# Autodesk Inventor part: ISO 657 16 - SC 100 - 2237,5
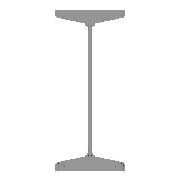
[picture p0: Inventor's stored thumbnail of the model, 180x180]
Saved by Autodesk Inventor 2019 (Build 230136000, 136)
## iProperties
_CCFamilyMember: 1
_CCFamilyDisplayName: ISO 657/16 - 1980 - Poutres en acier laminées à chaud - Partie 16: profilés en H (série métrique) - Cotes et propriétés de section
_FrameMemberDoc: Frame Member File
_Version: 15.0.0
_GetPNFromCC: 1
Created: 2018-07
Part Number: ISO 657 16 - SC 100 - 2237,5
Material: Acier, doux
Description: Poutres en acier laminées à chaud - Partie 16: profilés en H (série métrique) - Cotes et propriétés de section
Document SubType Name: Modeling
Standard: ISO
Designer: Fabian Perrée
Standard Revision: First edition 1980-02-15
Standards Organization: ISO
Language: fr-FR
Size Designation: SC 100
Categories: <MemberInstance><Categories><Category DisplayName="Profilés" InternalName="089c4875-fa83-4c05-b084-43b9cc11f5ed" Mnemonic="GRDR"><CategoryParameter DisplayName=
Stock Number: SC 100
Density: 7.85 g/cm^3
Appearance: Semi-poli
Mass: 44309.5 g
Surface Area: 12051.7 cm^2
Volume: 5644.52 cm^3
IsCustomPart: 1
G_W: 100,000 mm
G_H: 100,000 mm
+00612AE5-4A21-40A4-B490-CD8F624E81A5+DETAILDECOUPE1: Angle de coupe 90,00 deg
+1A323659-953F-4F35-8181-0827E3868009+DETAILDECOUPE2: Angle de coupe 67,38 deg
G_L: 2237,500 mm
Author: Fabian Perrée
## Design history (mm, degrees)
node "Plan de départ"
node "Plan de fin"
sketch "Esquisse"
  geometry: L1 (-3, 0)-(-3, -26.266); L2 (-13.33, -38.149)-(-44.835, -42.577); L3 (-50, -48.518)-(-50, -50); L4 (-50, -50)-(0, -50); L5 (-26.5, -50)-(-26.5, -40); L6 (-61.333, 0)-(81.777, 0); L7 (0, 0)-(0, -50); L8 (0, -60)-(0, 80); L9 (3, 0)-(3, -26.266); L10 (13.33, -38.149)-(44.835, -42.577); L11 (50, -48.518)-(50, -50); L12 (50, -50)-(0, -50); L13 (-3, 0)-(0, 0); L14 (-3, 0)-(-3, 26.266); L15 (-13.33, 38.149)-(-44.835, 42.577); L16 (-50, 48.518)-(-50, 50); L17 (-50, 50)-(0, 50); L18 (50, 48.518)-(50, 50); L19 (13.33, 38.149)-(44.835, 42.577); L20 (3, 0)-(3, 26.266); L21 (50, 50)-(0, 50); L22 (0, 108)-(0, -88) reference; L23 (-89.955, 0)-(110.399, 0) reference; A1 r 6 centre (-44, 48.518) between (-50, 48.518) and (-44.835, 42.577); A2 r 6 centre (44, 48.518) between (44.835, 42.577) and (50, 48.518); A3 r 6 centre (44, -48.518) between (50, -48.518) and (44.835, -42.577); A4 r 6 centre (-44, -48.518) between (-44.835, -42.577) and (-50, -48.518); A5 r 12 centre (-15, 26.266) between (-3, 26.266) and (-13.33, 38.149); A6 r 12 centre (15, 26.266) between (13.33, 38.149) and (3, 26.266); A7 r 12 centre (15, -26.266) between (3, -26.266) and (13.33, -38.149); A8 r 12 centre (-15, -26.266) between (-13.33, -38.149) and (-3, -26.266); 14 further points
  constraints: 42 end point, 24 point on line, 17 symmetric about line, 16 point on circle, 16 tangent, 8 centre point, 6 equal radius, 4 collinear, 2 perpendicular, 12 other
  dimensions: "d1" = 10 vertical distance of L3.end L5.end (= G_T1); "d2" = 23.5 distance between parallel lines of L5 L3 (= -0.25 x G_T + 0.25 x G_W); "d3" = 3 distance between parallel lines of L1 L7 (= 0.5 x G_T); "d4" = 50 distance between parallel lines of L7 L3 (= 0.5 x G_W); "d9" = 50 distance from line of L1.start L4 (= 0.5 x G_H); "d14" = 98 deg angle of L2 L1 (= G_NG); "d15" = 6 radius of A1 (= G_ER); "d16" = 12 radius of A5 (= G_IR)
extrude "Corps" new body sketch "Esquisse" stored distance "d5" = 2237.5 (= G_L); taper "d6" = 0 deg
node "Driven Length"
  sketch "Sketch3"
    geometry: L1 (0, 0)-(10, 0) reference
    constraints: 2 end point, 1 horizontal
  workplane "Work Plane3"
  sketch "Sketch4"
    geometry: L1 (-2, 87.5)-(12, 87.5) reference; L2 (-2, 2325)-(12, 2325) reference
    dimensions: "d20" = 2237.5 distance between parallel lines of L1 L2 (derived)
node "Plan de construction4"
feature "Scission1"
node "Plan de construction5"
feature "Scission2"
body "Solid1"
other parameters: "G_W" = 100 (= G_H) [user parameter; used in 2 equation terms], "G_H" = 100 [user parameter; used in 2 equation terms], "G_T" = 6 [user parameter; used in 2 equation terms], "G_T1" = 10 [user parameter; used in 1 equation term], "G_L" = 2237.5 (= d20) [user parameter; used in 1 equation term], "G_ER" = 6 [user parameter; used in 1 equation term], "G_IR" = 12 [user parameter; used in 1 equation term], "G_NG" = 98 deg [user parameter; used in 1 equation term], "G_OFFSET_START" = -87.5 [user parameter; used in 1 equation term], "d17" = 87.5 (= -G_OFFSET_START), "d18" = 2325 (= G_OFFSET_END + B_L), "B_L" = 2375 [user parameter; used in 1 equation term], "d19" = 90 deg
